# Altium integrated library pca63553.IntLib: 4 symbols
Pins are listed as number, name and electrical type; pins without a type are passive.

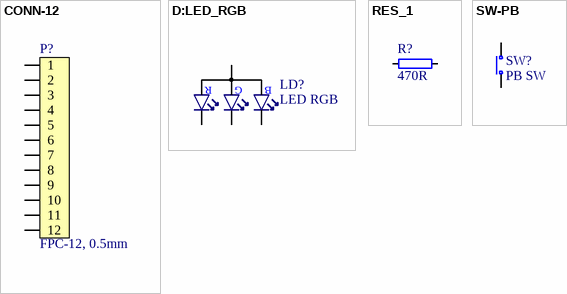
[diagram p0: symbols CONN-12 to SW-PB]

## CONN-12
designator P?, comment FPC-12, 0.5mm
0.5mm pitch, bottom side contact, side entry SMD FPC connector; Part Number: 10051922-1210ELF; Manufacturer: FCI; Artikkelnr Noca: N.A.
footprint 10051922-1210ELF
pins: 1, 2, 3, 4, 5, 6, 7, 8, 9, 10, 11, 12

## D:LED_RGB
designator LD?, comment LED RGB
3.5 x 2.8 mm Surface Mount RGB LED; Part Number: AAA3528LSEEZGKQBKS; Manufacturer: Kingbright Company LLC; Artikkelnr Noca: N.A.
footprint L3528_RGB
pins: 1 C_RED, 2 C_GREEN, 3 C_BLUE, 4 A

## RES_1
designator R?, comment 470R
Resistor, ±1%, 0.05W; Part Number: R0201-470; Note: Chip Res 1%; Artikkelnr Noca: N.A.
footprint RESC0603X03L_C
pins: 1, 2

## SW-PB
designator SW?, comment PB SW
Tactile Switch, SPNO, SMD, 160gf, 5.1x5.1x1.5mm; Part Number: Switch-PB-5.1x5.1mm-SMD; Manufacturer: C&K Components; Manufacturer Part Number: PTS525 SM15 SMTR2 LFS; Artikkelnr Noca: N.A.
footprint Switch-PB-5.1x5.1mm-SMD
pins: 1 N.O, 2 COM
